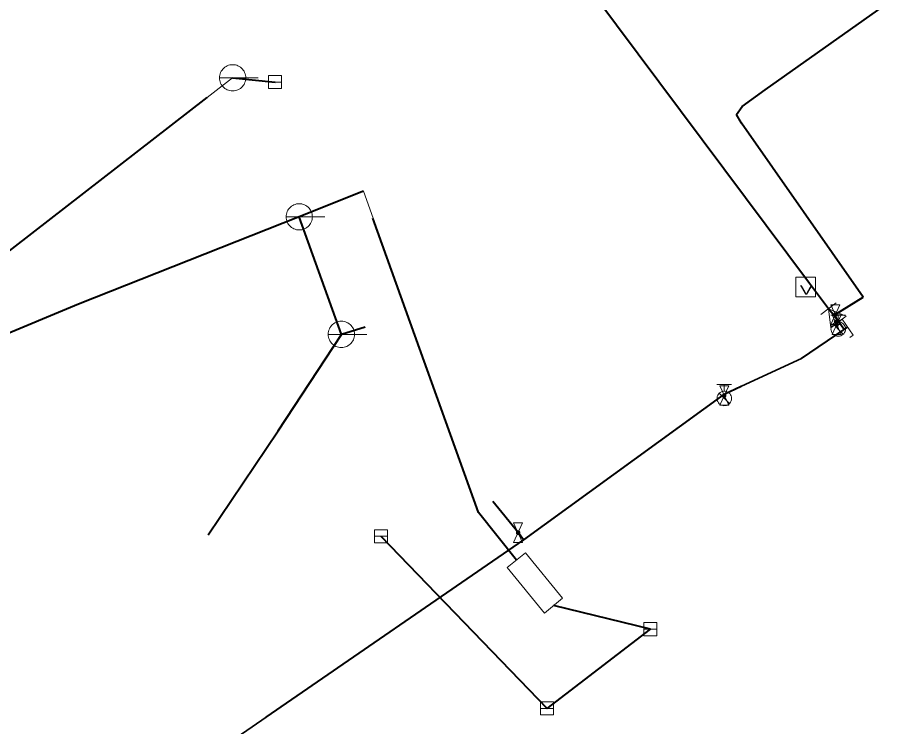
# Model space of a CAD drawing. Extents: x -968691 to -140888, y -1376050 to -879856.
# Drawn here: x -647594.9 to -647528.6, y -1059042.2 to -1058987.7 of the extents above; entities that cross this region are included whole.
import ezdxf
from ezdxf.enums import TextEntityAlignment as Align

# ---------------------------------------------------------------- set-up
doc = ezdxf.new("R2010")
doc.units = 0
doc.header["$LTSCALE"] = 4.8
for name, pattern in [('DASH_DOUBLE_DOT', [9.2, 5, -1.2, 0.3, -1.2, 0.3, -1.2]), ('DOTTED', [1.5, 0.3, -1.2]), ('LONG_DASHED', [7.5, 6, -1.5])]:
    doc.linetypes.add(name, pattern=pattern)
doc.layers.add('1', color=7, linetype='Continuous', lineweight=13)

msp = doc.modelspace()

# ---------------------------------------------------------------- hatches: boundary and pattern name
at = {"layer": '1'}
for points in [[(-647531.96, -1059010.546), (-647531.962, -1059010.522), (-647531.968, -1059010.499), (-647531.979, -1059010.477), (-647531.993, -1059010.458), (-647532.011, -1059010.441), (-647532.031, -1059010.428), (-647532.054, -1059010.419), (-647532.077, -1059010.415), (-647532.101, -1059010.414), (-647532.125, -1059010.418), (-647532.148, -1059010.426), (-647532.169, -1059010.438), (-647532.187, -1059010.454), (-647532.202, -1059010.473), (-647532.213, -1059010.494), (-647532.221, -1059010.517), (-647532.224, -1059010.541), (-647532.223, -1059010.565), (-647532.217, -1059010.588), (-647532.207, -1059010.61), (-647532.194, -1059010.63), (-647532.177, -1059010.647), (-647532.157, -1059010.661), (-647532.135, -1059010.671), (-647532.112, -1059010.677), (-647532.088, -1059010.678), (-647532.064, -1059010.675), (-647532.041, -1059010.668), (-647532.019, -1059010.656), (-647532, -1059010.642), (-647531.985, -1059010.623), (-647531.972, -1059010.603), (-647531.964, -1059010.58), (-647531.96, -1059010.556)], [(-647531.858, -1059011.31), (-647531.86, -1059011.287), (-647531.866, -1059011.265), (-647531.876, -1059011.244), (-647531.889, -1059011.225), (-647531.905, -1059011.208), (-647531.924, -1059011.195), (-647531.945, -1059011.186), (-647531.967, -1059011.18), (-647531.99, -1059011.178), (-647532.013, -1059011.18), (-647532.035, -1059011.186), (-647532.056, -1059011.195), (-647532.075, -1059011.208), (-647532.091, -1059011.225), (-647532.104, -1059011.244), (-647532.114, -1059011.265), (-647532.12, -1059011.287), (-647532.122, -1059011.31), (-647532.12, -1059011.333), (-647532.114, -1059011.355), (-647532.104, -1059011.376), (-647532.091, -1059011.395), (-647532.075, -1059011.411), (-647532.056, -1059011.424), (-647532.035, -1059011.434), (-647532.013, -1059011.44), (-647531.99, -1059011.442), (-647531.967, -1059011.44), (-647531.945, -1059011.434), (-647531.924, -1059011.424), (-647531.905, -1059011.411), (-647531.889, -1059011.395), (-647531.876, -1059011.376), (-647531.866, -1059011.355), (-647531.86, -1059011.333)], [(-647540.478, -1059016.75), (-647540.48, -1059016.726), (-647540.487, -1059016.703), (-647540.497, -1059016.681), (-647540.511, -1059016.662), (-647540.529, -1059016.645), (-647540.549, -1059016.632), (-647540.572, -1059016.623), (-647540.595, -1059016.619), (-647540.619, -1059016.618), (-647540.643, -1059016.622), (-647540.666, -1059016.63), (-647540.687, -1059016.642), (-647540.705, -1059016.658), (-647540.72, -1059016.677), (-647540.732, -1059016.698), (-647540.739, -1059016.721), (-647540.742, -1059016.745), (-647540.741, -1059016.769), (-647540.735, -1059016.792), (-647540.725, -1059016.814), (-647540.712, -1059016.834), (-647540.695, -1059016.851), (-647540.675, -1059016.865), (-647540.653, -1059016.875), (-647540.63, -1059016.881), (-647540.606, -1059016.882), (-647540.582, -1059016.879), (-647540.559, -1059016.872), (-647540.538, -1059016.861), (-647540.519, -1059016.846), (-647540.503, -1059016.827), (-647540.491, -1059016.807), (-647540.482, -1059016.784), (-647540.478, -1059016.76)], [(-647556.298, -1059027.28), (-647556.3, -1059027.256), (-647556.307, -1059027.233), (-647556.317, -1059027.211), (-647556.331, -1059027.192), (-647556.349, -1059027.175), (-647556.369, -1059027.162), (-647556.392, -1059027.153), (-647556.415, -1059027.149), (-647556.439, -1059027.148), (-647556.463, -1059027.152), (-647556.486, -1059027.16), (-647556.507, -1059027.172), (-647556.525, -1059027.188), (-647556.54, -1059027.207), (-647556.552, -1059027.228), (-647556.559, -1059027.251), (-647556.562, -1059027.275), (-647556.561, -1059027.299), (-647556.555, -1059027.322), (-647556.545, -1059027.344), (-647556.532, -1059027.364), (-647556.515, -1059027.381), (-647556.495, -1059027.395), (-647556.473, -1059027.405), (-647556.45, -1059027.411), (-647556.426, -1059027.412), (-647556.402, -1059027.409), (-647556.379, -1059027.402), (-647556.358, -1059027.391), (-647556.339, -1059027.376), (-647556.323, -1059027.357), (-647556.311, -1059027.337), (-647556.302, -1059027.314), (-647556.298, -1059027.29)]]:
    msp.add_hatch(color=256, dxfattribs=at).paths.add_polyline_path(points)

# ---------------------------------------------------------------- linework, layer by layer
for p, q in [((-647579.338, -1058992.37), (-647576.361, -1058992.37)), ((-647575.57, -1058992.7), (-647574.57, -1058992.7)), ((-647574.228, -1059003.04), (-647571.252, -1059003.04)), ((-647569.99, -1059012.06), (-647573.22, -1059003.04)), ((-647533.198, -1059010.535), (-647532.022, -1059009.645)), ((-647532.429, -1059010.581), (-647531.311, -1059010.581)), ((-647531.87, -1059011.092), (-647531.87, -1059010.581)), ((-647531.475, -1059012.046), (-647532.265, -1059011.255)), ((-647531.87, -1059011.65), (-647531.99, -1059011.31)), ((-647570.998, -1059012.06), (-647568.022, -1059012.06)), ((-647568.17, -1059011.5), (-647569.99, -1059012.06)), ((-647541.169, -1059015.91), (-647540.051, -1059015.91)), ((-647540.61, -1059016.422), (-647540.61, -1059015.91)), ((-647540.215, -1059017.375), (-647541.005, -1059016.585)), ((-647567.45, -1059027.56), (-647566.45, -1059027.56)), ((-647566.95, -1059027.56), (-647554.2, -1059040.77)), ((-647546.28, -1059034.69), (-647553.71, -1059032.885)), ((-647554.2, -1059040.77), (-647546.28, -1059034.69)), ((-647546.78, -1059034.69), (-647545.78, -1059034.69)), ((-647554.7, -1059040.77), (-647553.7, -1059040.77))]:
    msp.add_line(p, q, dxfattribs=at)
at = {"layer": '1', "linetype": 'DASH_DOUBLE_DOT', "lineweight": 40}
for p, q in [((-647569.99, -1059012.06), (-647573.22, -1059003.04)), ((-647532.184, -1059010.63), (-647532.092, -1059010.546)), ((-647568.17, -1059011.5), (-647569.99, -1059012.06)), ((-647540.61, -1059016.65), (-647556.01, -1059027.84)), ((-647556.01, -1059027.84), (-647594.1, -1059054.06)), ((-647566.95, -1059027.56), (-647554.2, -1059040.77)), ((-647546.28, -1059034.69), (-647553.71, -1059032.885)), ((-647554.2, -1059040.77), (-647546.28, -1059034.69))]:
    msp.add_line(p, q, dxfattribs=at)
at = {"layer": '1', "linetype": 'LONG_DASHED', "lineweight": 40}
for p, q in [((-647532.184, -1059010.63), (-647532.61, -1059010.09)), ((-647531.94, -1059010.94), (-647532.184, -1059010.63)), ((-647531.87, -1059011.65), (-647531.99, -1059011.31)), ((-647531.41, -1059011.69), (-647531.94, -1059010.94)), ((-647534.69, -1059013.91), (-647531.41, -1059011.69)), ((-647531.41, -1059011.69), (-647531.15, -1059011.51))]:
    msp.add_line(p, q, dxfattribs=at)
at = {"layer": '1', "lineweight": 35}
for p, q in [((-647532.184, -1059010.63), (-647532.61, -1059010.09)), ((-647532.184, -1059010.63), (-647532.092, -1059010.546)), ((-647531.94, -1059010.94), (-647532.184, -1059010.63)), ((-647531.41, -1059011.69), (-647531.94, -1059010.94)), ((-647534.69, -1059013.91), (-647531.41, -1059011.69)), ((-647531.41, -1059011.69), (-647531.15, -1059011.51)), ((-647540.61, -1059016.65), (-647534.69, -1059013.91)), ((-647540.61, -1059016.65), (-647556.01, -1059027.84)), ((-647556.01, -1059027.84), (-647594.1, -1059054.06))]:
    msp.add_line(p, q, dxfattribs=at)
at = {"layer": '1', "linetype": 'DOTTED', "lineweight": 40}
msp.add_line((-647540.61, -1059016.65), (-647534.69, -1059013.91), dxfattribs=at)
at = {"layer": '1', "linetype": 'DASH_DOUBLE_DOT'}
for p, q in [((-647555.86, -1059028.84), (-647557.26, -1059029.96)), ((-647553.01, -1059032.32), (-647555.86, -1059028.84))]:
    msp.add_line(p, q, dxfattribs=at)
at = {"layer": '1', "linetype": 'DASH_DOUBLE_DOT', "lineweight": 40}
for points in [[(-647532.092, -1059010.546), (-647529.959, -1059009.197), (-647539.29, -1058995.84), (-647539.66, -1058995.19), (-647539.24, -1058994.56), (-647537.46, -1058993.28), (-647528.4, -1058986.88), (-647516.03, -1058979.12), (-647519.65, -1058973.26), (-647530.64, -1058959.05), (-647535.07, -1058953.43), (-647549.25, -1058935.34), (-647563.74, -1058917.26), (-647562.952, -1058916.613)], [(-647599.27, -1059008.59), (-647578.33, -1058992.37), (-647575.07, -1058992.7)], [(-647556.56, -1059029.4), (-647559.46, -1059025.73), (-647568.3, -1059001.08), (-647573.22, -1059003.04)], [(-647573.22, -1059003.04), (-647590.165, -1059009.75), (-647603.21, -1059015.19), (-647607.28, -1059017.39)], [(-647580.22, -1059027.44), (-647574.83, -1059019.46), (-647569.99, -1059012.06)], [(-647540.61, -1059016.98), (-647540.61, -1059016.75), (-647540.61, -1059016.65)], [(-647556.01, -1059027.84), (-647556.43, -1059027.28), (-647558.36, -1059024.89)]]:
    msp.add_lwpolyline(points, dxfattribs=at)
at = {"layer": '1', "lineweight": 35}
msp.add_lwpolyline([(-647532.092, -1059010.546), (-647529.959, -1059009.197), (-647539.29, -1058995.84), (-647539.66, -1058995.19), (-647539.24, -1058994.56), (-647537.46, -1058993.28), (-647528.4, -1058986.88), (-647516.03, -1058979.12), (-647519.65, -1058973.26), (-647530.64, -1058959.05), (-647535.07, -1058953.43), (-647549.25, -1058935.34), (-647563.74, -1058917.26), (-647562.952, -1058916.613)], dxfattribs=at)
at = {"layer": '1', "linetype": 'LONG_DASHED', "lineweight": 40}
for points in [[(-647532.61, -1059010.09), (-647534.06, -1059008.17), (-647553.35, -1058982.32), (-647570.9, -1058971.33)], [(-647531.99, -1059011.31), (-647532.14, -1059011.07), (-647531.94, -1059010.94)]]:
    msp.add_lwpolyline(points, dxfattribs=at)
at = {"layer": '1'}
for points in [[(-647532.61, -1059010.09), (-647534.06, -1059008.17), (-647553.35, -1058982.32), (-647570.9, -1058971.33)], [(-647599.27, -1059008.59), (-647578.33, -1058992.37), (-647575.07, -1058992.7)], [(-647556.56, -1059029.4), (-647559.46, -1059025.73), (-647568.3, -1059001.08), (-647573.22, -1059003.04)], [(-647573.22, -1059003.04), (-647590.165, -1059009.75), (-647603.21, -1059015.19), (-647607.28, -1059017.39)], [(-647531.99, -1059011.31), (-647532.14, -1059011.07), (-647531.94, -1059010.94)], [(-647531.816, -1059011.053), (-647531.567, -1059010.886), (-647530.733, -1059012.134), (-647530.983, -1059012.3)], [(-647580.22, -1059027.44), (-647574.83, -1059019.46), (-647569.99, -1059012.06)], [(-647540.61, -1059016.98), (-647540.61, -1059016.75), (-647540.61, -1059016.65)], [(-647556.01, -1059027.84), (-647556.43, -1059027.28), (-647558.36, -1059024.89)]]:
    msp.add_lwpolyline(points, dxfattribs=at)
for points in [[(-647578.33, -1058991.362), (-647578.435, -1058991.368), (-647578.539, -1058991.384), (-647578.641, -1058991.411), (-647578.739, -1058991.449), (-647578.833, -1058991.497), (-647578.921, -1058991.554), (-647579.004, -1058991.621), (-647579.079, -1058991.696), (-647579.145, -1058991.778), (-647579.202, -1058991.865), (-647579.249, -1058991.96), (-647579.287, -1058992.059), (-647579.315, -1058992.16), (-647579.331, -1058992.265), (-647579.338, -1058992.37), (-647579.331, -1058992.475), (-647579.315, -1058992.58), (-647579.287, -1058992.682), (-647579.249, -1058992.78), (-647579.202, -1058992.873), (-647579.145, -1058992.963), (-647579.079, -1058993.045), (-647579.004, -1058993.119), (-647578.921, -1058993.185), (-647578.833, -1058993.243), (-647578.739, -1058993.291), (-647578.641, -1058993.329), (-647578.539, -1058993.356), (-647578.435, -1058993.372), (-647578.33, -1058993.378), (-647578.224, -1058993.372), (-647578.119, -1058993.356), (-647578.018, -1058993.329), (-647577.92, -1058993.291), (-647577.825, -1058993.243), (-647577.737, -1058993.185), (-647577.655, -1058993.119), (-647577.58, -1058993.045), (-647577.514, -1058992.963), (-647577.457, -1058992.873), (-647577.408, -1058992.78), (-647577.37, -1058992.682), (-647577.344, -1058992.58), (-647577.328, -1058992.475), (-647577.322, -1058992.37), (-647577.328, -1058992.265), (-647577.344, -1058992.16), (-647577.37, -1058992.059), (-647577.408, -1058991.96), (-647577.457, -1058991.865), (-647577.514, -1058991.778), (-647577.58, -1058991.696), (-647577.655, -1058991.621), (-647577.737, -1058991.554), (-647577.825, -1058991.497), (-647577.92, -1058991.449), (-647578.018, -1058991.411), (-647578.119, -1058991.384), (-647578.224, -1058991.368)], [(-647575.57, -1058993.2), (-647574.57, -1058993.2), (-647574.57, -1058992.2), (-647575.57, -1058992.2)], [(-647573.22, -1059002.032), (-647573.325, -1059002.038), (-647573.429, -1059002.054), (-647573.531, -1059002.082), (-647573.63, -1059002.12), (-647573.724, -1059002.167), (-647573.812, -1059002.225), (-647573.894, -1059002.291), (-647573.969, -1059002.366), (-647574.035, -1059002.448), (-647574.093, -1059002.536), (-647574.14, -1059002.63), (-647574.178, -1059002.729), (-647574.206, -1059002.831), (-647574.222, -1059002.935), (-647574.228, -1059003.04), (-647574.222, -1059003.145), (-647574.206, -1059003.25), (-647574.178, -1059003.352), (-647574.14, -1059003.45), (-647574.093, -1059003.544), (-647574.035, -1059003.633), (-647573.969, -1059003.715), (-647573.894, -1059003.789), (-647573.812, -1059003.855), (-647573.724, -1059003.913), (-647573.63, -1059003.961), (-647573.531, -1059003.999), (-647573.429, -1059004.026), (-647573.325, -1059004.042), (-647573.22, -1059004.048), (-647573.115, -1059004.042), (-647573.01, -1059004.026), (-647572.908, -1059003.999), (-647572.81, -1059003.961), (-647572.716, -1059003.913), (-647572.627, -1059003.855), (-647572.545, -1059003.789), (-647572.471, -1059003.715), (-647572.405, -1059003.633), (-647572.347, -1059003.544), (-647572.299, -1059003.45), (-647572.261, -1059003.352), (-647572.234, -1059003.25), (-647572.218, -1059003.145), (-647572.212, -1059003.04), (-647572.218, -1059002.935), (-647572.234, -1059002.831), (-647572.261, -1059002.729), (-647572.299, -1059002.63), (-647572.347, -1059002.536), (-647572.405, -1059002.448), (-647572.471, -1059002.366), (-647572.545, -1059002.291), (-647572.627, -1059002.225), (-647572.716, -1059002.167), (-647572.81, -1059002.12), (-647572.908, -1059002.082), (-647573.01, -1059002.054), (-647573.115, -1059002.038)], [(-647535.11, -1059009.18), (-647533.61, -1059009.18), (-647533.61, -1059007.68), (-647535.11, -1059007.68)], [(-647531.25, -1059010.664), (-647532.426, -1059011.555), (-647532.61, -1059010.09)], [(-647532.442, -1059009.796), (-647531.742, -1059009.796), (-647532.442, -1059011.296), (-647531.742, -1059011.296)], [(-647532.34, -1059010.56), (-647531.64, -1059010.56), (-647532.34, -1059012.06), (-647531.64, -1059012.06)], [(-647531.96, -1059010.546), (-647531.962, -1059010.522), (-647531.968, -1059010.499), (-647531.979, -1059010.477), (-647531.993, -1059010.458), (-647532.011, -1059010.441), (-647532.031, -1059010.428), (-647532.054, -1059010.419), (-647532.077, -1059010.415), (-647532.101, -1059010.414), (-647532.125, -1059010.418), (-647532.148, -1059010.426), (-647532.169, -1059010.438), (-647532.187, -1059010.454), (-647532.202, -1059010.473), (-647532.213, -1059010.494), (-647532.221, -1059010.517), (-647532.224, -1059010.541), (-647532.223, -1059010.565), (-647532.217, -1059010.588), (-647532.207, -1059010.61), (-647532.194, -1059010.63), (-647532.177, -1059010.647), (-647532.157, -1059010.661), (-647532.135, -1059010.671), (-647532.112, -1059010.677), (-647532.088, -1059010.678), (-647532.064, -1059010.675), (-647532.041, -1059010.668), (-647532.019, -1059010.656), (-647532, -1059010.642), (-647531.985, -1059010.623), (-647531.972, -1059010.603), (-647531.964, -1059010.58), (-647531.96, -1059010.556)], [(-647569.99, -1059011.052), (-647570.095, -1059011.058), (-647570.199, -1059011.074), (-647570.301, -1059011.102), (-647570.4, -1059011.14), (-647570.494, -1059011.187), (-647570.582, -1059011.245), (-647570.664, -1059011.311), (-647570.739, -1059011.386), (-647570.805, -1059011.468), (-647570.863, -1059011.556), (-647570.91, -1059011.65), (-647570.948, -1059011.749), (-647570.976, -1059011.851), (-647570.992, -1059011.955), (-647570.998, -1059012.06), (-647570.992, -1059012.165), (-647570.976, -1059012.27), (-647570.948, -1059012.372), (-647570.91, -1059012.47), (-647570.863, -1059012.564), (-647570.805, -1059012.653), (-647570.739, -1059012.735), (-647570.664, -1059012.809), (-647570.582, -1059012.875), (-647570.494, -1059012.933), (-647570.4, -1059012.981), (-647570.301, -1059013.019), (-647570.199, -1059013.046), (-647570.095, -1059013.062), (-647569.99, -1059013.068), (-647569.885, -1059013.062), (-647569.78, -1059013.046), (-647569.678, -1059013.019), (-647569.58, -1059012.981), (-647569.486, -1059012.933), (-647569.397, -1059012.875), (-647569.315, -1059012.809), (-647569.241, -1059012.735), (-647569.175, -1059012.653), (-647569.117, -1059012.564), (-647569.069, -1059012.47), (-647569.031, -1059012.372), (-647569.004, -1059012.27), (-647568.988, -1059012.165), (-647568.982, -1059012.06), (-647568.988, -1059011.955), (-647569.004, -1059011.851), (-647569.031, -1059011.749), (-647569.069, -1059011.65), (-647569.117, -1059011.556), (-647569.175, -1059011.468), (-647569.241, -1059011.386), (-647569.315, -1059011.311), (-647569.397, -1059011.245), (-647569.486, -1059011.187), (-647569.58, -1059011.14), (-647569.678, -1059011.102), (-647569.78, -1059011.074), (-647569.885, -1059011.058)], [(-647531.311, -1059011.651), (-647531.32, -1059011.554), (-647531.345, -1059011.46), (-647531.386, -1059011.372), (-647531.442, -1059011.292), (-647531.511, -1059011.223), (-647531.591, -1059011.167), (-647531.679, -1059011.126), (-647531.773, -1059011.101), (-647531.87, -1059011.092), (-647531.967, -1059011.101), (-647532.061, -1059011.126), (-647532.149, -1059011.167), (-647532.229, -1059011.223), (-647532.298, -1059011.292), (-647532.354, -1059011.372), (-647532.395, -1059011.46), (-647532.42, -1059011.554), (-647532.429, -1059011.651), (-647532.42, -1059011.748), (-647532.395, -1059011.842), (-647532.354, -1059011.93), (-647532.298, -1059012.01), (-647532.229, -1059012.079), (-647532.149, -1059012.135), (-647532.061, -1059012.176), (-647531.967, -1059012.201), (-647531.87, -1059012.209), (-647531.773, -1059012.201), (-647531.679, -1059012.176), (-647531.591, -1059012.135), (-647531.511, -1059012.079), (-647531.442, -1059012.01), (-647531.386, -1059011.93), (-647531.345, -1059011.842), (-647531.32, -1059011.748)], [(-647531.858, -1059011.31), (-647531.86, -1059011.287), (-647531.866, -1059011.265), (-647531.876, -1059011.244), (-647531.889, -1059011.225), (-647531.905, -1059011.208), (-647531.924, -1059011.195), (-647531.945, -1059011.186), (-647531.967, -1059011.18), (-647531.99, -1059011.178), (-647532.013, -1059011.18), (-647532.035, -1059011.186), (-647532.056, -1059011.195), (-647532.075, -1059011.208), (-647532.091, -1059011.225), (-647532.104, -1059011.244), (-647532.114, -1059011.265), (-647532.12, -1059011.287), (-647532.122, -1059011.31), (-647532.12, -1059011.333), (-647532.114, -1059011.355), (-647532.104, -1059011.376), (-647532.091, -1059011.395), (-647532.075, -1059011.411), (-647532.056, -1059011.424), (-647532.035, -1059011.434), (-647532.013, -1059011.44), (-647531.99, -1059011.442), (-647531.967, -1059011.44), (-647531.945, -1059011.434), (-647531.924, -1059011.424), (-647531.905, -1059011.411), (-647531.889, -1059011.395), (-647531.876, -1059011.376), (-647531.866, -1059011.355), (-647531.86, -1059011.333)], [(-647540.96, -1059016), (-647540.26, -1059016), (-647540.96, -1059017.5), (-647540.26, -1059017.5)], [(-647540.051, -1059016.98), (-647540.06, -1059016.881), (-647540.087, -1059016.784), (-647540.131, -1059016.694), (-647540.19, -1059016.612), (-647540.262, -1059016.543), (-647540.346, -1059016.488), (-647540.438, -1059016.449), (-647540.536, -1059016.427), (-647540.636, -1059016.422), (-647540.736, -1059016.436), (-647540.831, -1059016.467), (-647540.919, -1059016.515), (-647540.998, -1059016.578), (-647541.063, -1059016.654), (-647541.114, -1059016.74), (-647541.149, -1059016.834), (-647541.167, -1059016.933), (-647541.166, -1059017.033), (-647541.148, -1059017.132), (-647541.112, -1059017.226), (-647541.06, -1059017.311), (-647540.994, -1059017.387), (-647540.915, -1059017.449), (-647540.826, -1059017.496), (-647540.731, -1059017.526), (-647540.631, -1059017.539), (-647540.531, -1059017.534), (-647540.433, -1059017.511), (-647540.341, -1059017.47), (-647540.258, -1059017.415), (-647540.186, -1059017.345), (-647540.128, -1059017.263), (-647540.085, -1059017.172), (-647540.059, -1059017.075)], [(-647540.478, -1059016.75), (-647540.48, -1059016.726), (-647540.487, -1059016.703), (-647540.497, -1059016.681), (-647540.511, -1059016.662), (-647540.529, -1059016.645), (-647540.549, -1059016.632), (-647540.572, -1059016.623), (-647540.595, -1059016.619), (-647540.619, -1059016.618), (-647540.643, -1059016.622), (-647540.666, -1059016.63), (-647540.687, -1059016.642), (-647540.705, -1059016.658), (-647540.72, -1059016.677), (-647540.732, -1059016.698), (-647540.739, -1059016.721), (-647540.742, -1059016.745), (-647540.741, -1059016.769), (-647540.735, -1059016.792), (-647540.725, -1059016.814), (-647540.712, -1059016.834), (-647540.695, -1059016.851), (-647540.675, -1059016.865), (-647540.653, -1059016.875), (-647540.63, -1059016.881), (-647540.606, -1059016.882), (-647540.582, -1059016.879), (-647540.559, -1059016.872), (-647540.538, -1059016.861), (-647540.519, -1059016.846), (-647540.503, -1059016.827), (-647540.491, -1059016.807), (-647540.482, -1059016.784), (-647540.478, -1059016.76)], [(-647556.78, -1059026.53), (-647556.08, -1059026.53), (-647556.78, -1059028.03), (-647556.08, -1059028.03)], [(-647567.45, -1059028.06), (-647566.45, -1059028.06), (-647566.45, -1059027.06), (-647567.45, -1059027.06)], [(-647556.298, -1059027.28), (-647556.3, -1059027.256), (-647556.307, -1059027.233), (-647556.317, -1059027.211), (-647556.331, -1059027.192), (-647556.349, -1059027.175), (-647556.369, -1059027.162), (-647556.392, -1059027.153), (-647556.415, -1059027.149), (-647556.439, -1059027.148), (-647556.463, -1059027.152), (-647556.486, -1059027.16), (-647556.507, -1059027.172), (-647556.525, -1059027.188), (-647556.54, -1059027.207), (-647556.552, -1059027.228), (-647556.559, -1059027.251), (-647556.562, -1059027.275), (-647556.561, -1059027.299), (-647556.555, -1059027.322), (-647556.545, -1059027.344), (-647556.532, -1059027.364), (-647556.515, -1059027.381), (-647556.495, -1059027.395), (-647556.473, -1059027.405), (-647556.45, -1059027.411), (-647556.426, -1059027.412), (-647556.402, -1059027.409), (-647556.379, -1059027.402), (-647556.358, -1059027.391), (-647556.339, -1059027.376), (-647556.323, -1059027.357), (-647556.311, -1059027.337), (-647556.302, -1059027.314), (-647556.298, -1059027.29)], [(-647546.78, -1059035.19), (-647545.78, -1059035.19), (-647545.78, -1059034.19), (-647546.78, -1059034.19)], [(-647554.7, -1059041.27), (-647553.7, -1059041.27), (-647553.7, -1059040.27), (-647554.7, -1059040.27)]]:
    msp.add_lwpolyline(points, close=True, dxfattribs=at)
at = {"layer": '1', "linetype": 'DASH_DOUBLE_DOT'}
msp.add_lwpolyline([(-647557.26, -1059029.96), (-647554.41, -1059033.45), (-647553.01, -1059032.32)], dxfattribs=at)

# ---------------------------------------------------------------- texts
at = {"layer": '1', "width": 1.55}
msp.add_text('V', height=0.7, dxfattribs=at).set_placement((-647534.321, -1059009.009), align=Align.CENTER)

doc.saveas('drawing.dxf')
